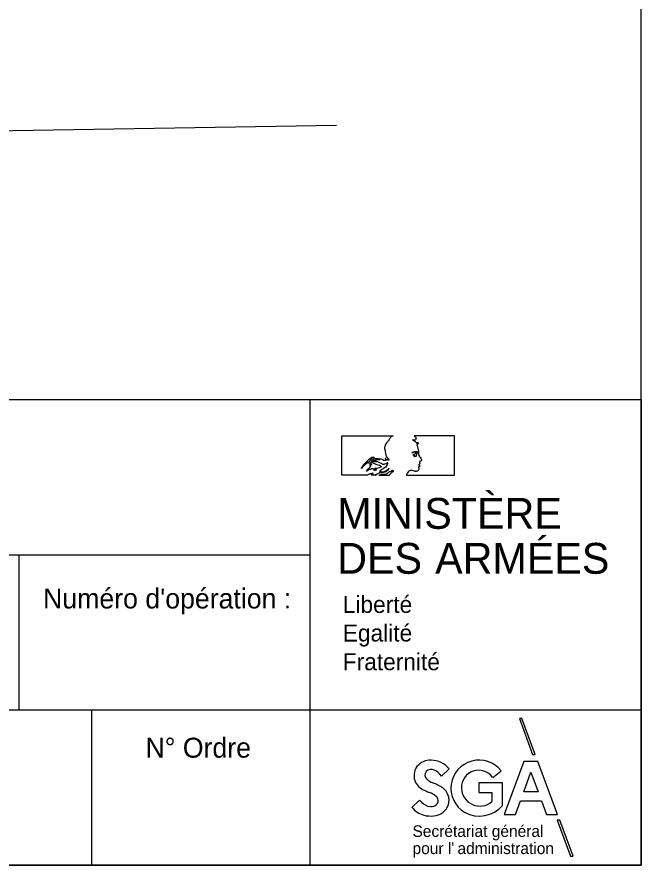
# Model space of a CAD drawing. Extents: x 37864 to 38032, y 453991 to 454052.
# Drawn here: x 38023.04 to 38032.43, y 453990.82 to 454003.57 of the extents above; entities that cross this region are included whole.
import ezdxf

# ---------------------------------------------------------------- set-up
doc = ezdxf.new("R2010")
doc.units = 0
doc.layers.add('PS_Dim', color=7, linetype='Continuous')

msp = doc.modelspace()

# ---------------------------------------------------------------- linework, layer by layer
at = {"layer": 'DEFPOINTS'}
for p, q in [((38027.447, 453997.816), (38027.447, 453990.816)), ((38027.93, 453997.271), (38028.7, 453997.271)), ((38027.93, 453996.679), (38027.93, 453997.271)), ((38029.626, 453997.271), (38029.018, 453997.271)), ((38029.626, 453996.679), (38029.626, 453997.271)), ((38028.318, 453996.679), (38027.93, 453996.679)), ((38028.439, 453996.679), (38028.369, 453996.679)), ((38028.487, 453996.679), (38028.645, 453996.679)), ((38028.901, 453996.679), (38029.626, 453996.679)), ((38017.598, 453995.483), (38027.447, 453995.483)), ((38023.069, 453995.483), (38023.069, 453993.149)), ((38017.598, 453993.149), (38032.431, 453993.149)), ((38024.164, 453993.149), (38024.164, 453990.816)), ((38030.6, 453993.018), (38030.8, 453992.48)), ((38030.639, 453993.018), (38030.6, 453993.018)), ((38030.838, 453992.48), (38030.639, 453993.018)), ((38030.8, 453992.48), (38030.838, 453992.48)), ((38029.427, 453992.155), (38029.546, 453992.262)), ((38030.199, 453992.135), (38030.328, 453992.233)), ((38029.1, 453991.793), (38028.982, 453991.684)), ((38031.209, 453991.489), (38031.17, 453991.489)), ((38031.17, 453991.489), (38031.369, 453990.951)), ((38031.408, 453990.951), (38031.209, 453991.489)), ((38031.369, 453990.951), (38031.408, 453990.951))]:
    msp.add_line(p, q, dxfattribs=at)
for points in [[(37950.431, 453990.816), (38032.431, 453990.816), (38032.431, 454048.216), (37950.431, 454048.216)], [(37992.431, 453997.816), (38032.431, 453997.816), (38032.431, 453990.816), (37992.431, 453990.816)], [(38028.326, 453996.874), (38028.317, 453996.869), (38028.295, 453996.852), (38028.274, 453996.834), (38028.255, 453996.814), (38028.237, 453996.794), (38028.227, 453996.782), (38028.226, 453996.782), (38028.225, 453996.783), (38028.226, 453996.785), (38028.234, 453996.798), (38028.248, 453996.818), (38028.259, 453996.838), (38028.265, 453996.851), (38028.268, 453996.855), (38028.271, 453996.857), (38028.283, 453996.865), (38028.298, 453996.878), (38028.317, 453996.898), (38028.336, 453996.916), (38028.35, 453996.929), (38028.364, 453996.94), (38028.379, 453996.949), (38028.39, 453996.952), (38028.4, 453996.953), (38028.409, 453996.952), (38028.416, 453996.95), (38028.417, 453996.949), (38028.414, 453996.946), (38028.41, 453996.944), (38028.404, 453996.943), (38028.402, 453996.94), (38028.399, 453996.94), (38028.397, 453996.942), (38028.398, 453996.945), (38028.392, 453996.94), (38028.379, 453996.929), (38028.366, 453996.918), (38028.358, 453996.909), (38028.352, 453996.897), (38028.345, 453996.884), (38028.34, 453996.879), (38028.335, 453996.875), (38028.332, 453996.874), (38028.334, 453996.873), (38028.334, 453996.87), (38028.33, 453996.865), (38028.327, 453996.861), (38028.324, 453996.86), (38028.322, 453996.86), (38028.322, 453996.862), (38028.323, 453996.865), (38028.326, 453996.869), (38028.329, 453996.872), (38028.326, 453996.872)], [(38028.418, 453996.752), (38028.418, 453996.755), (38028.42, 453996.758), (38028.423, 453996.76), (38028.429, 453996.761), (38028.435, 453996.764), (38028.439, 453996.766), (38028.441, 453996.767), (38028.443, 453996.765), (38028.445, 453996.763), (38028.449, 453996.762), (38028.451, 453996.761), (38028.451, 453996.759), (38028.448, 453996.757), (38028.443, 453996.755), (38028.436, 453996.754), (38028.43, 453996.754), (38028.425, 453996.752), (38028.42, 453996.751)], [(38031.176, 453991.578), (38030.879, 453992.372), (38030.668, 453992.372), (38030.37, 453991.578), (38030.54, 453991.578), (38030.615, 453991.781), (38030.931, 453991.781), (38031.006, 453991.578)], [(38030.773, 453992.214), (38030.881, 453991.919), (38030.665, 453991.919)]]:
    msp.add_lwpolyline(points, close=True, dxfattribs=at)
for points in [[(38028.7, 453997.271), (38028.692, 453997.267), (38028.682, 453997.262), (38028.671, 453997.255), (38028.664, 453997.249)], [(38029.018, 453997.271), (38029.028, 453997.264), (38029.038, 453997.254), (38029.044, 453997.245), (38029.046, 453997.241), (38029.047, 453997.235), (38029.045, 453997.23), (38029.044, 453997.226), (38029.042, 453997.22), (38029.039, 453997.214), (38029.036, 453997.211), (38029.029, 453997.209), (38029.018, 453997.208), (38029.004, 453997.209), (38028.992, 453997.211), (38029.004, 453997.206), (38029.013, 453997.202), (38029.026, 453997.193), (38029.036, 453997.183), (38029.043, 453997.175), (38029.046, 453997.172), (38029.051, 453997.171), (38029.055, 453997.171), (38029.056, 453997.169), (38029.056, 453997.167), (38029.054, 453997.165), (38029.052, 453997.164), (38029.052, 453997.161), (38029.052, 453997.159), (38029.054, 453997.159), (38029.057, 453997.159), (38029.059, 453997.16), (38029.061, 453997.163), (38029.062, 453997.168), (38029.065, 453997.171), (38029.067, 453997.172), (38029.072, 453997.17), (38029.076, 453997.166), (38029.077, 453997.16), (38029.077, 453997.154), (38029.074, 453997.148), (38029.066, 453997.142), (38029.06, 453997.137), (38029.058, 453997.134), (38029.059, 453997.131), (38029.06, 453997.128), (38029.063, 453997.124), (38029.069, 453997.105), (38029.075, 453997.083), (38029.08, 453997.062), (38029.083, 453997.051), (38029.085, 453997.033), (38029.084, 453997.016), (38029.082, 453997.005), (38029.082, 453996.998), (38029.083, 453996.992), (38029.085, 453996.985), (38029.089, 453996.976)], [(38028.664, 453997.249), (38028.655, 453997.239), (38028.646, 453997.227), (38028.64, 453997.215), (38028.636, 453997.207), (38028.635, 453997.202), (38028.633, 453997.2), (38028.629, 453997.197), (38028.623, 453997.192), (38028.614, 453997.182), (38028.606, 453997.17), (38028.598, 453997.157), (38028.588, 453997.139), (38028.58, 453997.125), (38028.575, 453997.111), (38028.572, 453997.101), (38028.572, 453997.093), (38028.573, 453997.082), (38028.576, 453997.065), (38028.579, 453997.05), (38028.583, 453997.029), (38028.586, 453997.011), (38028.588, 453997.004), (38028.59, 453996.997), (38028.59, 453996.991), (38028.591, 453996.984), (38028.592, 453996.979), (38028.594, 453996.973), (38028.595, 453996.97), (38028.597, 453996.967), (38028.599, 453996.965), (38028.599, 453996.962), (38028.6, 453996.959), (38028.602, 453996.957), (38028.603, 453996.957), (38028.603, 453996.952), (38028.604, 453996.95), (38028.614, 453996.939), (38028.622, 453996.929), (38028.63, 453996.917), (38028.634, 453996.911), (38028.634, 453996.908), (38028.631, 453996.906), (38028.626, 453996.906), (38028.619, 453996.907), (38028.61, 453996.911), (38028.603, 453996.916), (38028.598, 453996.921), (38028.588, 453996.932), (38028.584, 453996.936), (38028.582, 453996.936), (38028.581, 453996.935), (38028.582, 453996.933), (38028.585, 453996.929), (38028.593, 453996.92), (38028.598, 453996.915), (38028.599, 453996.91), (38028.598, 453996.907), (38028.595, 453996.905), (38028.591, 453996.904), (38028.587, 453996.906), (38028.582, 453996.906), (38028.579, 453996.905), (38028.578, 453996.902), (38028.578, 453996.896)], [(38028.985, 453997.016), (38028.999, 453997.025), (38029.014, 453997.031), (38029.025, 453997.034), (38029.036, 453997.036), (38029.044, 453997.038), (38029.05, 453997.037), (38029.056, 453997.035), (38029.065, 453997.033), (38029.069, 453997.031), (38029.07, 453997.028), (38029.07, 453997.021), (38029.066, 453997.015), (38029.06, 453997.01), (38029.057, 453997.008), (38029.057, 453997.006), (38029.06, 453997.004), (38029.061, 453997.002), (38029.061, 453996.999), (38029.058, 453996.997), (38029.054, 453996.997), (38029.051, 453996.994), (38029.046, 453996.99), (38029.048, 453996.987), (38029.047, 453996.982), (38029.046, 453996.977), (38029.047, 453996.97), (38029.046, 453996.965), (38029.043, 453996.961), (38029.036, 453996.96), (38029.027, 453996.959), (38029.019, 453996.961), (38029.013, 453996.963), (38029.02, 453996.963), (38029.026, 453996.964), (38029.029, 453996.966), (38029.029, 453996.97), (38029.029, 453996.972), (38029.027, 453996.974), (38029.024, 453996.971), (38029.023, 453996.974), (38029.021, 453996.976), (38029.017, 453996.977), (38029.012, 453996.978), (38029.005, 453996.98), (38029.001, 453996.984), (38029.001, 453996.986), (38029.006, 453996.987), (38029.01, 453996.987), (38029.013, 453996.986), (38029.014, 453996.988), (38029.015, 453996.992), (38029.017, 453996.995), (38029.019, 453996.996), (38029.023, 453996.996), (38029.024, 453996.998), (38029.027, 453997), (38029.033, 453997.005), (38029.04, 453997.009), (38029.046, 453997.015), (38029.048, 453997.02), (38029.047, 453997.022), (38029.042, 453997.024), (38029.031, 453997.025), (38029.02, 453997.025)], [(38029.02, 453997.025), (38029.01, 453997.023), (38028.997, 453997.02), (38028.985, 453997.016)], [(38028.42, 453996.776), (38028.411, 453996.772), (38028.402, 453996.771), (38028.398, 453996.773), (38028.397, 453996.775), (38028.403, 453996.776), (38028.391, 453996.776), (38028.39, 453996.779), (38028.382, 453996.777), (38028.372, 453996.774), (38028.364, 453996.772), (38028.355, 453996.766), (38028.347, 453996.763), (38028.337, 453996.759), (38028.328, 453996.754), (38028.317, 453996.746), (38028.308, 453996.741), (38028.301, 453996.739), (38028.299, 453996.74), (38028.3, 453996.743), (38028.306, 453996.747), (38028.31, 453996.751), (38028.309, 453996.753), (38028.308, 453996.755), (38028.313, 453996.761), (38028.326, 453996.773), (38028.34, 453996.784), (38028.346, 453996.789), (38028.346, 453996.793), (38028.355, 453996.802), (38028.358, 453996.808), (38028.361, 453996.813), (38028.367, 453996.818), (38028.372, 453996.82), (38028.368, 453996.821), (38028.367, 453996.824), (38028.362, 453996.822), (38028.357, 453996.822), (38028.353, 453996.824), (38028.352, 453996.826), (38028.353, 453996.827), (38028.356, 453996.83), (38028.359, 453996.83), (38028.357, 453996.832), (38028.357, 453996.834), (38028.36, 453996.837), (38028.366, 453996.839), (38028.373, 453996.84), (38028.377, 453996.843), (38028.379, 453996.845), (38028.369, 453996.843), (38028.359, 453996.844), (38028.353, 453996.846), (38028.351, 453996.847), (38028.351, 453996.85), (38028.356, 453996.858), (38028.363, 453996.871), (38028.372, 453996.879), (38028.378, 453996.884), (38028.383, 453996.887), (38028.386, 453996.887), (38028.387, 453996.885), (38028.386, 453996.881), (38028.384, 453996.876), (38028.38, 453996.873)], [(38028.578, 453996.896), (38028.574, 453996.898), (38028.568, 453996.9), (38028.56, 453996.9), (38028.554, 453996.901), (38028.551, 453996.905), (38028.549, 453996.909), (38028.546, 453996.912), (38028.542, 453996.914), (38028.536, 453996.915), (38028.521, 453996.919), (38028.503, 453996.922), (38028.476, 453996.926), (38028.448, 453996.928), (38028.432, 453996.927), (38028.421, 453996.926), (38028.409, 453996.922), (38028.399, 453996.916), (38028.391, 453996.91), (38028.382, 453996.9), (38028.377, 453996.894), (38028.375, 453996.891), (38028.375, 453996.889), (38028.377, 453996.888), (38028.379, 453996.888), (38028.382, 453996.89), (38028.389, 453996.894), (38028.396, 453996.898), (38028.407, 453996.901), (38028.425, 453996.907), (38028.44, 453996.91), (38028.457, 453996.914), (38028.472, 453996.917), (38028.489, 453996.918), (38028.502, 453996.917), (38028.493, 453996.916), (38028.481, 453996.915), (38028.468, 453996.912), (38028.449, 453996.907), (38028.435, 453996.902), (38028.421, 453996.899), (38028.408, 453996.896), (38028.398, 453996.893), (38028.391, 453996.89)], [(38028.391, 453996.89), (38028.408, 453996.89), (38028.434, 453996.888), (38028.46, 453996.884), (38028.485, 453996.877), (38028.507, 453996.868), (38028.521, 453996.86), (38028.528, 453996.854), (38028.534, 453996.849), (38028.543, 453996.845), (38028.551, 453996.845)], [(38029.089, 453996.976), (38029.097, 453996.963), (38029.104, 453996.953), (38029.113, 453996.939), (38029.122, 453996.925), (38029.128, 453996.913), (38029.129, 453996.906), (38029.128, 453996.899), (38029.125, 453996.894), (38029.12, 453996.891), (38029.112, 453996.889), (38029.104, 453996.886), (38029.099, 453996.884), (38029.097, 453996.881), (38029.097, 453996.877), (38029.097, 453996.872), (38029.099, 453996.866), (38029.103, 453996.861), (38029.104, 453996.854), (38029.103, 453996.849), (38029.099, 453996.844), (38029.092, 453996.839), (38029.087, 453996.837), (38029.085, 453996.836), (38029.086, 453996.835), (38029.089, 453996.833), (38029.093, 453996.832), (38029.095, 453996.831), (38029.096, 453996.828), (38029.097, 453996.825), (38029.1, 453996.82), (38029.1, 453996.815), (38029.097, 453996.811), (38029.093, 453996.807), (38029.087, 453996.803), (38029.084, 453996.798), (38029.084, 453996.795), (38029.084, 453996.792), (38029.086, 453996.788), (38029.089, 453996.781), (38029.088, 453996.774), (38029.086, 453996.763), (38029.083, 453996.754), (38029.078, 453996.748), (38029.067, 453996.741), (38029.057, 453996.738), (38029.047, 453996.737), (38029.04, 453996.737), (38029.035, 453996.739), (38029.033, 453996.74), (38029.028, 453996.741), (38029.018, 453996.742), (38029.003, 453996.745), (38028.988, 453996.748), (38028.973, 453996.75), (38028.961, 453996.75), (38028.951, 453996.747), (38028.944, 453996.744), (38028.937, 453996.738), (38028.928, 453996.729), (38028.918, 453996.716), (38028.913, 453996.707), (38028.908, 453996.698), (38028.903, 453996.686), (38028.901, 453996.679)], [(38028.38, 453996.873), (38028.377, 453996.872), (38028.385, 453996.871), (38028.394, 453996.869), (38028.402, 453996.867), (38028.407, 453996.865), (38028.408, 453996.863), (38028.404, 453996.861), (38028.411, 453996.86), (38028.42, 453996.859), (38028.424, 453996.856), (38028.422, 453996.854), (38028.418, 453996.854), (38028.442, 453996.847), (38028.473, 453996.838), (38028.496, 453996.828), (38028.515, 453996.817), (38028.523, 453996.811), (38028.528, 453996.807), (38028.527, 453996.806), (38028.515, 453996.802), (38028.491, 453996.792), (38028.455, 453996.782), (38028.436, 453996.778), (38028.428, 453996.78), (38028.427, 453996.776), (38028.42, 453996.776)], [(38028.516, 453996.741), (38028.518, 453996.74), (38028.519, 453996.739), (38028.518, 453996.738), (38028.514, 453996.737), (38028.513, 453996.736), (38028.511, 453996.735), (38028.507, 453996.735), (38028.505, 453996.732), (38028.503, 453996.73), (38028.502, 453996.728), (38028.501, 453996.727), (38028.499, 453996.727), (38028.497, 453996.726), (38028.496, 453996.725), (38028.497, 453996.724), (38028.501, 453996.725), (38028.505, 453996.725), (38028.514, 453996.726), (38028.537, 453996.728), (38028.551, 453996.73), (38028.564, 453996.733), (38028.577, 453996.738), (38028.59, 453996.746), (38028.606, 453996.756), (38028.618, 453996.765), (38028.629, 453996.776), (38028.635, 453996.782), (38028.637, 453996.784), (38028.639, 453996.783), (38028.639, 453996.781), (38028.638, 453996.776), (38028.633, 453996.768), (38028.627, 453996.76), (38028.619, 453996.752), (38028.609, 453996.746), (38028.6, 453996.738), (38028.589, 453996.731), (38028.583, 453996.728), (38028.574, 453996.725), (38028.557, 453996.721), (38028.534, 453996.717), (38028.509, 453996.714), (38028.492, 453996.71), (38028.478, 453996.706), (38028.467, 453996.702), (38028.457, 453996.697), (38028.448, 453996.692), (38028.444, 453996.689), (38028.441, 453996.687), (38028.44, 453996.687), (38028.439, 453996.687), (38028.437, 453996.687), (38028.432, 453996.684), (38028.43, 453996.682), (38028.431, 453996.68), (38028.432, 453996.679), (38028.435, 453996.68), (38028.439, 453996.683), (38028.445, 453996.686), (38028.454, 453996.69), (38028.46, 453996.692), (38028.454, 453996.688), (38028.445, 453996.683), (38028.439, 453996.679)], [(38028.551, 453996.845), (38028.557, 453996.846), (38028.565, 453996.847), (38028.576, 453996.85), (38028.598, 453996.858), (38028.607, 453996.863), (38028.614, 453996.869), (38028.617, 453996.872), (38028.62, 453996.87), (38028.618, 453996.865), (38028.617, 453996.857), (38028.615, 453996.85), (38028.612, 453996.843), (38028.609, 453996.839), (38028.608, 453996.835), (38028.609, 453996.833), (38028.61, 453996.83), (38028.614, 453996.83), (38028.615, 453996.83), (38028.613, 453996.828), (38028.609, 453996.828), (38028.603, 453996.825), (38028.599, 453996.822), (38028.598, 453996.821), (38028.599, 453996.82), (38028.602, 453996.82), (38028.601, 453996.819), (38028.598, 453996.818), (38028.595, 453996.817), (38028.594, 453996.814), (38028.594, 453996.809), (38028.591, 453996.808), (38028.588, 453996.806), (38028.588, 453996.804), (38028.589, 453996.803), (38028.591, 453996.803), (38028.596, 453996.804), (38028.601, 453996.806), (38028.599, 453996.804), (38028.588, 453996.799), (38028.577, 453996.794), (38028.567, 453996.789), (38028.563, 453996.788), (38028.56, 453996.787), (38028.558, 453996.785), (38028.559, 453996.783), (38028.561, 453996.783), (38028.565, 453996.784), (38028.568, 453996.785), (38028.568, 453996.784), (38028.56, 453996.779), (38028.541, 453996.769), (38028.513, 453996.753), (38028.511, 453996.75), (38028.51, 453996.748), (38028.509, 453996.747), (38028.507, 453996.747), (38028.504, 453996.747), (38028.503, 453996.744), (38028.502, 453996.741), (38028.501, 453996.739), (38028.503, 453996.737), (38028.507, 453996.738), (38028.511, 453996.74), (38028.516, 453996.741)], [(38028.369, 453996.679), (38028.373, 453996.682), (38028.383, 453996.688), (38028.392, 453996.695), (38028.402, 453996.7), (38028.403, 453996.701), (38028.401, 453996.703), (38028.398, 453996.703), (38028.395, 453996.704), (38028.39, 453996.703), (38028.387, 453996.703), (38028.382, 453996.704), (38028.378, 453996.705), (38028.374, 453996.705), (38028.37, 453996.703), (38028.365, 453996.701), (38028.358, 453996.699), (38028.35, 453996.697), (38028.341, 453996.694), (38028.333, 453996.691), (38028.327, 453996.688), (38028.321, 453996.683), (38028.318, 453996.679)], [(38028.645, 453996.679), (38028.649, 453996.684), (38028.659, 453996.696), (38028.677, 453996.715), (38028.691, 453996.728), (38028.702, 453996.737), (38028.705, 453996.741), (38028.706, 453996.744), (38028.704, 453996.743), (38028.701, 453996.741), (38028.697, 453996.738), (38028.692, 453996.734), (38028.689, 453996.732), (38028.687, 453996.732), (38028.687, 453996.733), (38028.687, 453996.735), (38028.689, 453996.736), (38028.699, 453996.744), (38028.703, 453996.747), (38028.7, 453996.746), (38028.699, 453996.747), (38028.699, 453996.749), (38028.697, 453996.749), (38028.691, 453996.749), (38028.686, 453996.747), (38028.675, 453996.743), (38028.667, 453996.737), (38028.66, 453996.731), (38028.658, 453996.728), (38028.654, 453996.728), (38028.652, 453996.729), (38028.648, 453996.729), (38028.638, 453996.723), (38028.627, 453996.716), (38028.617, 453996.708), (38028.604, 453996.7), (38028.598, 453996.697), (38028.598, 453996.699), (38028.594, 453996.698), (38028.589, 453996.696), (38028.579, 453996.691), (38028.569, 453996.689), (38028.561, 453996.689), (38028.541, 453996.689), (38028.532, 453996.688), (38028.52, 453996.686), (38028.509, 453996.683), (38028.487, 453996.679)], [(38030.348, 453991.71), (38030.348, 453992.053), (38029.99, 453992.053), (38029.99, 453991.905), (38030.187, 453991.905), (38030.187, 453991.77)]]:
    msp.add_lwpolyline(points, dxfattribs=at)
for centre, radius, start, end in [((38029.249, 453992.161), 0.234, 144.1987, 205.9594), ((38029.255, 453992.143), 0.249, 86.0104, 141.5681), ((38029.274, 453992.043), 0.348, 38.7989, 90.3107), ((38029.994, 453991.972), 0.423, 38, 239.1837), ((38029.26, 453992.17), 0.0806, 139.5578, 228.1206), ((38029.273, 453992.152), 0.102, 62.0259, 136.6599), ((38029.212, 453992.003), 0.263, 35.1811, 65.6046), ((38029.988, 453991.983), 0.259, 35.7277, 182.0849), ((38029.294, 453992.209), 0.296, 210.4008, 249.6927), ((38029.365, 453992.267), 0.223, 224.6353, 253.3725), ((38028.86, 453991.051), 1.095, 57.5939, 66.2786), ((38029.47, 453992.531), 0.661, 245.0513, 250.5103), ((38029.123, 453991.578), 0.353, 51.5524, 68.988), ((38029.315, 453991.791), 0.227, 343.0107, 54.4277), ((38030.006, 453991.979), 0.277, 181.1083, 310.8878), ((38029.311, 453991.949), 0.263, 216.582, 251.897), ((38029.296, 453991.787), 0.0819, 358.7093, 55.2832), ((38029.308, 453991.778), 0.0704, 310.8873, 5.5663), ((38029.277, 453991.932), 0.385, 219.9839, 252.525), ((38029.265, 453991.843), 0.148, 256.1236, 307.2747), ((38029.3, 453991.798), 0.244, 272.6923, 342.4014), ((38029.999, 453992.019), 0.466, 241.584, 318.4992), ((38029.269, 453992.04), 0.487, 257.2793, 275.0071)]:
    msp.add_arc(centre, radius, start, end, dxfattribs=at)
at = {"layer": 'PS_Dim'}
msp.add_lwpolyline([(38027.847, 454001.939), (38022.98, 454001.859), (38017.923, 454001.855), (38012.951, 454001.773), (38008.007, 454001.708), (38002.72, 454001.64), (37997.98, 454001.622), (37993.014, 454001.592), (37991.113, 454001.604)], dxfattribs=at)

# ---------------------------------------------------------------- texts
at = {"layer": 'DEFPOINTS'}
for s, height, p in [('MINISTÈRE', 0.4641, (38027.86, 453995.873)), ('ARMÉES', 0.4641, (38029.333, 453995.197)), ('DES', 0.4641, (38027.86, 453995.197)), ("Numéro d'opération :", 0.3, (38023.435, 453994.675)), ('Liberté', 0.2553, (38027.944, 453994.608)), ('Egalité', 0.2553, (38027.944, 453994.178)), ('Fraternité', 0.2553, (38027.944, 453993.746)), ('N° Ordre', 0.3, (38024.976, 453992.431)), ('Secrétariat général', 0.17444, (38028.992, 453991.239)), ("pour l'", 0.1744, (38028.993, 453990.981)), ('administration', 0.17444, (38029.669, 453990.981))]:
    msp.add_text(s, height=height, rotation=360, dxfattribs=at).set_placement(p)

doc.saveas('drawing.dxf')
